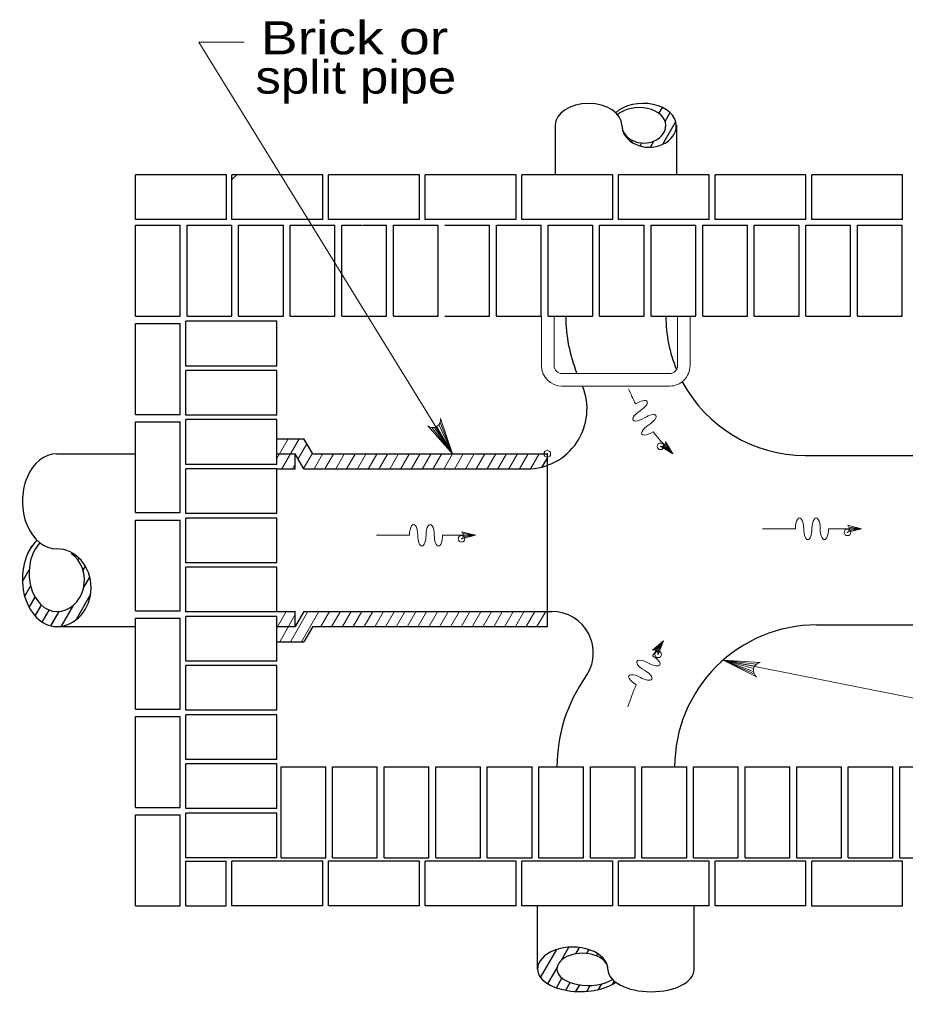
# Model space of a CAD drawing. Extents: x 750.7 to 784.7, y 860.1 to 882.1.
# Drawn here: x 767.038 to 771.324, y 862.671 to 867.382 of the extents above; entities that cross this region are included whole.
import ezdxf

# ---------------------------------------------------------------- set-up
doc = ezdxf.new("R2010")
doc.units = 0
doc.header["$LTSCALE"] = 0.064
doc.header["$PDMODE"] = 32
doc.header["$PDSIZE"] = 0.032
doc.layers.add('1', color=7, linetype='Continuous', lineweight=13)

msp = doc.modelspace()

# ---------------------------------------------------------------- linework, layer by layer
at = {"layer": '1', "lineweight": 25}
for p, q in [((770.13133, 866.92742), (770.148, 866.9565)), ((769.92375, 866.93008), (769.92617, 866.93433)), ((770.1615, 866.889), (770.18592, 866.93133)), ((769.62983, 866.87017), (769.62983, 866.63142)), ((770.15042, 866.77867), (770.21317, 866.88783)), ((770.21542, 866.87017), (770.21542, 866.63142)), ((769.96617, 866.82208), (769.96783, 866.825)), ((769.99925, 866.78867), (770.00383, 866.7965)), ((770.04075, 866.76983), (770.04933, 866.78475)), ((770.08975, 866.76408), (770.10683, 866.79383)), ((768.03883, 866.63142), (767.59925, 866.63142)), ((767.59925, 866.41508), (767.59925, 866.63142)), ((768.03883, 866.41508), (768.03883, 866.63142)), ((768.06542, 866.60733), (768.09075, 866.63158)), ((768.06542, 866.41508), (768.06542, 866.63142)), ((768.50492, 866.63142), (768.06542, 866.63142)), ((768.50492, 866.41508), (768.50492, 866.63142)), ((768.53292, 866.41508), (768.53292, 866.63142)), ((768.68067, 866.63142), (768.53292, 866.63142)), ((768.97242, 866.63142), (768.63892, 866.63142)), ((768.97242, 866.41508), (768.97242, 866.63142)), ((769.44, 866.63142), (769.00042, 866.63142)), ((769.00042, 866.41508), (769.00042, 866.63142)), ((769.44, 866.41508), (769.44, 866.63142)), ((769.9075, 866.63142), (769.46792, 866.63142)), ((769.46792, 866.41508), (769.46792, 866.63142)), ((769.9075, 866.41508), (769.9075, 866.63142)), ((770.375, 866.63142), (769.93542, 866.63142)), ((769.93542, 866.41508), (769.93542, 866.63142)), ((770.375, 866.41508), (770.375, 866.63142)), ((770.8425, 866.63142), (770.403, 866.63142)), ((770.403, 866.41508), (770.403, 866.63142)), ((770.8425, 866.41508), (770.8425, 866.63142)), ((771.31008, 866.63142), (770.8705, 866.63142)), ((770.8705, 866.41508), (770.8705, 866.63142)), ((771.31008, 866.41508), (771.31008, 866.63142)), ((768.03883, 866.41508), (767.59925, 866.41508)), ((767.59925, 866.38717), (767.81558, 866.38717)), ((767.59925, 865.94758), (767.59925, 866.38717)), ((767.84875, 865.94758), (767.84875, 866.38717)), ((767.84875, 866.38717), (768.065, 866.38717)), ((768.065, 865.94758), (768.065, 866.38717)), ((768.50492, 866.41508), (768.06542, 866.41508)), ((768.09817, 865.94758), (768.09817, 866.38717)), ((768.09817, 866.38717), (768.31442, 866.38717)), ((768.31442, 865.94758), (768.31442, 866.38717)), ((768.34758, 865.94758), (768.34758, 866.38717)), ((768.34758, 866.38717), (768.56392, 866.38717)), ((768.71075, 866.41508), (768.53292, 866.41508)), ((768.56392, 865.94758), (768.56392, 866.38717)), ((768.597, 865.94758), (768.597, 866.38717)), ((768.597, 866.38717), (768.69567, 866.38717)), ((768.97242, 866.41508), (768.68792, 866.41508)), ((768.69842, 866.38717), (768.81333, 866.38717)), ((768.81333, 865.94758), (768.81333, 866.38717)), ((768.8465, 865.94758), (768.8465, 866.38717)), ((768.8465, 866.38717), (769.06275, 866.38717)), ((769.44, 866.41508), (769.00042, 866.41508)), ((769.06275, 865.94758), (769.06275, 866.38717)), ((769.09592, 866.38717), (769.31225, 866.38717)), ((769.31225, 865.94758), (769.31225, 866.38717)), ((769.34533, 865.94758), (769.34533, 866.38717)), ((769.34533, 866.38717), (769.56167, 866.38717)), ((769.9075, 866.41508), (769.46792, 866.41508)), ((769.56167, 865.94758), (769.56167, 866.38717)), ((769.59483, 865.94758), (769.59483, 866.38717)), ((769.59483, 866.38717), (769.81108, 866.38717)), ((769.81108, 865.94758), (769.81108, 866.38717)), ((769.84425, 865.94758), (769.84425, 866.38717)), ((769.84425, 866.38717), (770.06058, 866.38717)), ((770.375, 866.41508), (769.93542, 866.41508)), ((770.06058, 865.94758), (770.06058, 866.38717)), ((770.09367, 865.94758), (770.09367, 866.38717)), ((770.09367, 866.38717), (770.31, 866.38717)), ((770.31, 865.94758), (770.31, 866.38717)), ((770.34317, 865.94758), (770.34317, 866.38717)), ((770.34317, 866.38717), (770.55942, 866.38717)), ((770.8425, 866.41508), (770.403, 866.41508)), ((770.55942, 865.94758), (770.55942, 866.38717)), ((770.59258, 865.94758), (770.59258, 866.38717)), ((770.59258, 866.38717), (770.80883, 866.38717)), ((770.80883, 865.94758), (770.80883, 866.38717)), ((770.842, 865.94758), (770.842, 866.38717)), ((770.842, 866.38717), (771.05833, 866.38717)), ((771.31008, 866.41508), (770.8705, 866.41508)), ((771.05833, 865.94758), (771.05833, 866.38717)), ((771.0915, 865.94758), (771.0915, 866.38717)), ((771.0915, 866.38717), (771.30775, 866.38717)), ((771.30775, 865.94758), (771.30775, 866.38717)), ((767.59925, 865.91183), (767.81558, 865.91192)), ((767.59925, 865.47233), (767.59925, 865.91183)), ((768.28308, 865.92225), (767.8435, 865.92225)), ((767.8435, 865.706), (767.8435, 865.92225)), ((767.84875, 865.94758), (768.065, 865.94758)), ((768.09817, 865.94758), (768.31442, 865.94758)), ((768.28308, 865.706), (768.28308, 865.92225)), ((768.34758, 865.94758), (768.56392, 865.94758)), ((768.597, 865.94758), (768.81333, 865.94758)), ((768.8465, 865.94758), (769.06275, 865.94758)), ((769.09592, 865.94758), (769.31225, 865.94758)), ((769.34533, 865.94758), (769.56167, 865.94758)), ((769.59483, 865.94758), (769.81108, 865.94758)), ((769.68058, 865.94758), (769.68058, 865.94742)), ((769.84425, 865.94758), (770.06058, 865.94758)), ((770.09367, 865.94758), (770.31, 865.94758)), ((770.16467, 865.94758), (770.16467, 865.94733)), ((770.34317, 865.94758), (770.55942, 865.94758)), ((770.59258, 865.94758), (770.80883, 865.94758)), ((770.842, 865.94758), (771.05833, 865.94758)), ((771.0915, 865.94758), (771.30775, 865.94758)), ((768.28308, 865.706), (767.8435, 865.706)), ((768.28308, 865.6845), (767.8435, 865.6845)), ((767.8435, 865.46817), (767.8435, 865.6845)), ((768.28308, 865.46817), (768.28308, 865.6845)), ((767.59925, 865.43658), (767.81558, 865.43658)), ((767.59925, 864.997), (767.59925, 865.43658)), ((768.28308, 865.46817), (767.8435, 865.46817)), ((768.28308, 865.44667), (767.8435, 865.44667)), ((767.8435, 865.23033), (767.8435, 865.44667)), ((768.28308, 865.23033), (768.28308, 865.44667)), ((768.28308, 865.35442), (768.414, 865.35442)), ((768.45633, 865.28142), (768.414, 865.35442)), ((767.21842, 865.28142), (767.59925, 865.28142)), ((768.28308, 865.28142), (768.372, 865.28142)), ((768.41433, 865.2085), (768.372, 865.28142)), ((768.372, 865.2085), (768.372, 865.28142)), ((768.45633, 865.28142), (769.59142, 865.28142)), ((769.567, 865.21808), (769.59142, 865.26042)), ((770.83842, 865.27358), (771.57217, 865.27358)), ((768.28308, 865.23033), (767.8435, 865.23033)), ((768.28308, 865.20883), (767.8435, 865.20883)), ((767.8435, 864.9925), (767.8435, 865.20883)), ((768.28308, 864.9925), (768.28308, 865.20883)), ((768.28308, 865.2085), (768.372, 865.2085)), ((768.41433, 865.2085), (769.49308, 865.2085)), ((768.28308, 864.9925), (767.8435, 864.9925)), ((768.28308, 864.971), (767.8435, 864.971)), ((767.8435, 864.75475), (767.8435, 864.971)), ((768.28308, 864.75475), (768.28308, 864.971)), ((767.59925, 864.96133), (767.81558, 864.96133)), ((767.59925, 864.52175), (767.59925, 864.96133)), ((767.08, 864.80275), (767.09758, 864.83342)), ((767.09758, 864.83967), (767.10025, 864.83808)), ((767.32117, 864.76758), (767.32642, 864.77675)), ((767.34542, 864.71875), (767.35667, 864.73833)), ((768.28308, 864.75475), (767.8435, 864.75475)), ((768.28308, 864.73317), (767.8435, 864.73317)), ((767.8435, 864.51692), (767.8435, 864.73317)), ((768.28308, 864.51692), (768.28308, 864.73317)), ((767.05242, 864.66392), (767.085, 864.72058)), ((767.34825, 864.63267), (767.37833, 864.68517)), ((767.0635, 864.59225), (767.09217, 864.64208)), ((767.085, 864.53867), (767.11367, 864.58858)), ((767.31167, 864.47825), (767.382, 864.60058)), ((767.11358, 864.49733), (767.14392, 864.55017)), ((767.24192, 864.44775), (767.3015, 864.5515)), ((767.1485, 864.46717), (767.18217, 864.52575)), ((767.19042, 864.44917), (767.23083, 864.5195)), ((768.28308, 864.51692), (767.8435, 864.51692)), ((768.28308, 864.49533), (767.8435, 864.49533)), ((767.8435, 864.27908), (767.8435, 864.49533)), ((768.28308, 864.51883), (768.372, 864.51883)), ((768.28308, 864.27908), (768.28308, 864.49533)), ((768.41433, 864.51883), (768.372, 864.44575)), ((768.372, 864.44575), (768.372, 864.51883)), ((768.41433, 864.51883), (769.6135, 864.51883)), ((767.21842, 864.44583), (767.59925, 864.44583)), ((767.59925, 864.486), (767.81558, 864.486)), ((767.59925, 864.0465), (767.59925, 864.486)), ((768.28308, 864.44575), (768.372, 864.44575)), ((768.45633, 864.44583), (768.414, 864.37292)), ((770.8935, 864.45367), (771.57217, 864.45367)), ((768.28308, 864.37292), (768.414, 864.37292)), ((768.28308, 864.27908), (767.8435, 864.27908)), ((768.28308, 864.25758), (767.8435, 864.25758)), ((767.8435, 864.04125), (767.8435, 864.25758)), ((768.28308, 864.04125), (768.28308, 864.25758)), ((768.28308, 864.04125), (767.8435, 864.04125)), ((767.59925, 864.01075), (767.81558, 864.01075)), ((767.59925, 863.57117), (767.59925, 864.01075)), ((768.28308, 864.01975), (767.8435, 864.01975)), ((767.8435, 863.80342), (767.8435, 864.01975)), ((768.28308, 863.80342), (768.28308, 864.01975)), ((768.28308, 863.80342), (767.8435, 863.80342)), ((768.28308, 863.78192), (767.8435, 863.78192)), ((767.8435, 863.56567), (767.8435, 863.78192)), ((768.28308, 863.56567), (768.28308, 863.78192)), ((768.30325, 863.32775), (768.30325, 863.76733)), ((768.30325, 863.76733), (768.5195, 863.76733)), ((768.5195, 863.32775), (768.5195, 863.76733)), ((768.55267, 863.32775), (768.55267, 863.76733)), ((768.55267, 863.76733), (768.769, 863.76733)), ((768.769, 863.32775), (768.769, 863.76733)), ((768.80217, 863.32775), (768.80217, 863.76733)), ((768.80217, 863.76733), (769.01842, 863.76733)), ((769.01842, 863.32775), (769.01842, 863.76733)), ((769.05158, 863.32775), (769.05158, 863.76733)), ((769.05158, 863.76733), (769.26783, 863.76733)), ((769.26783, 863.32775), (769.26783, 863.76733)), ((769.301, 863.32775), (769.301, 863.76733)), ((769.301, 863.76733), (769.51733, 863.76733)), ((769.51733, 863.32775), (769.51733, 863.76733)), ((769.5505, 863.32775), (769.5505, 863.76733)), ((769.5505, 863.76733), (769.76675, 863.76733)), ((769.638, 863.76733), (769.638, 863.76742)), ((769.76675, 863.32775), (769.76675, 863.76733)), ((769.79992, 863.32775), (769.79992, 863.76733)), ((769.79992, 863.76733), (770.01617, 863.76733)), ((770.01617, 863.32775), (770.01617, 863.76733)), ((770.04933, 863.32775), (770.04933, 863.76733)), ((770.04933, 863.76733), (770.26567, 863.76733)), ((770.20725, 863.76733), (770.20725, 863.7675)), ((770.26567, 863.32775), (770.26567, 863.76733)), ((770.29875, 863.32775), (770.29875, 863.76733)), ((770.29875, 863.76733), (770.51508, 863.76733)), ((770.51508, 863.32775), (770.51508, 863.76733)), ((770.54825, 863.32775), (770.54825, 863.76733)), ((770.54825, 863.76733), (770.7645, 863.76733)), ((770.7645, 863.32775), (770.7645, 863.76733)), ((770.79767, 863.32775), (770.79767, 863.76733)), ((770.79767, 863.76733), (771.014, 863.76733)), ((771.014, 863.32775), (771.014, 863.76733)), ((771.04708, 863.32775), (771.04708, 863.76733)), ((771.04708, 863.76733), (771.26342, 863.76733)), ((771.26342, 863.32775), (771.26342, 863.76733)), ((771.29658, 863.32775), (771.29658, 863.76733)), ((771.29658, 863.76733), (771.51283, 863.76733)), ((768.28308, 863.56567), (767.8435, 863.56567)), ((767.59925, 863.53542), (767.81558, 863.53542)), ((767.59925, 863.09592), (767.59925, 863.53542)), ((767.81558, 863.09592), (767.81558, 863.53542)), ((768.28308, 863.54408), (767.8435, 863.54408)), ((767.8435, 863.32783), (767.8435, 863.54408)), ((768.28308, 863.54408), (767.8435, 863.54408)), ((767.8435, 863.32783), (767.8435, 863.54408)), ((768.28308, 863.32783), (768.28308, 863.54408)), ((768.28308, 863.32783), (768.28308, 863.54408)), ((768.28308, 863.32783), (767.8435, 863.32783)), ((768.28308, 863.32783), (767.8435, 863.32783)), ((768.30325, 863.32775), (768.5195, 863.32775)), ((768.55267, 863.32775), (768.769, 863.32775)), ((768.80217, 863.32775), (769.01842, 863.32775)), ((769.05158, 863.32775), (769.26783, 863.32775)), ((769.301, 863.32775), (769.51733, 863.32775)), ((769.5505, 863.32775), (769.76675, 863.32775)), ((769.79992, 863.32775), (770.01617, 863.32775)), ((770.04933, 863.32775), (770.26567, 863.32775)), ((770.29875, 863.32775), (770.51508, 863.32775)), ((770.54825, 863.32775), (770.7645, 863.32775)), ((770.79767, 863.32775), (771.014, 863.32775)), ((771.04708, 863.32775), (771.26342, 863.32775)), ((771.29658, 863.32775), (771.51283, 863.32775)), ((768.03742, 863.09592), (768.03742, 863.31183)), ((768.06542, 863.09567), (768.06542, 863.31183)), ((768.53292, 863.0955), (768.53292, 863.31158)), ((769.00042, 863.09533), (769.00042, 863.31142)), ((769.46792, 863.09517), (769.46792, 863.31125)), ((769.93542, 863.09492), (769.93542, 863.31108)), ((770.403, 863.09475), (770.403, 863.31083)), ((770.8705, 863.09458), (770.8705, 863.31067)), ((767.59925, 863.09592), (767.81558, 863.09592)), ((767.8435, 863.09592), (768.03742, 863.09592)), ((768.50492, 863.09567), (768.06542, 863.09567)), ((768.97242, 863.0955), (768.53292, 863.0955)), ((769.44, 863.09533), (769.00042, 863.09533)), ((769.9075, 863.09517), (769.46792, 863.09517)), ((769.54367, 862.78842), (769.54367, 863.09533)), ((770.375, 863.09492), (769.93542, 863.09492)), ((770.30158, 862.78842), (770.30158, 863.09492)), ((770.8425, 863.09475), (770.403, 863.09475)), ((771.31008, 863.09458), (770.8705, 863.09458)), ((769.65983, 862.83258), (769.69583, 862.89525)), ((769.72992, 862.86358), (769.74733, 862.89383)), ((769.55883, 862.748), (769.63692, 862.88425)), ((769.783, 862.865), (769.79367, 862.8835)), ((769.82875, 862.85358), (769.83492, 862.86433)), ((769.86675, 862.82883), (769.86925, 862.83317)), ((769.594, 862.71817), (769.6385, 862.79533)), ((769.63533, 862.69908), (769.66225, 862.74575)), ((769.68075, 862.68708), (769.70225, 862.72433)), ((769.72967, 862.68117), (769.74808, 862.71308)), ((769.78225, 862.68158), (769.79883, 862.71033)), ((769.83958, 862.69033), (769.85567, 862.71817)), ((769.90658, 862.71558), (769.91558, 862.73133))]:
    msp.add_line(p, q, dxfattribs=at)
at = {"layer": '1'}
for p, q in [((769.56358, 865.94758), (769.56358, 865.70733)), ((769.62417, 865.94758), (769.62417, 865.70733)), ((770.22108, 865.94758), (770.22108, 865.70733)), ((770.28167, 865.94758), (770.28167, 865.70733)), ((769.662, 865.66958), (770.18325, 865.66958)), ((769.662, 865.60892), (770.18325, 865.60892)), ((769.03283, 865.40825), (769.13242, 865.28058)), ((769.04517, 865.40908), (769.13242, 865.28058)), ((769.05575, 865.41325), (769.13242, 865.28058)), ((769.06683, 865.42292), (769.13242, 865.28058)), ((769.07275, 865.43342), (769.13242, 865.28058)), ((768.28308, 865.2585), (768.33825, 865.35442)), ((768.30667, 865.2085), (768.3905, 865.35442)), ((768.3865, 865.2565), (768.4285, 865.3295)), ((770.19817, 865.28233), (770.15733, 865.32358)), ((768.41275, 865.21117), (768.45475, 865.28417)), ((768.4635, 865.2085), (768.50425, 865.27942)), ((768.51583, 865.2085), (768.55658, 865.2795)), ((768.56808, 865.2085), (768.60892, 865.27958)), ((768.62033, 865.2085), (768.66133, 865.27967)), ((768.67267, 865.2085), (768.71367, 865.27983)), ((768.72408, 865.207), (768.766, 865.27992)), ((768.77642, 865.20717), (768.81833, 865.28)), ((768.82883, 865.20725), (768.87067, 865.28008)), ((768.88117, 865.20733), (768.923, 865.28017)), ((768.9335, 865.20742), (768.97533, 865.28033)), ((768.98583, 865.2075), (769.02767, 865.28042)), ((769.03817, 865.20767), (769.08008, 865.2805)), ((769.0905, 865.20775), (769.13242, 865.28058)), ((769.14283, 865.20783), (769.18475, 865.28067)), ((769.19517, 865.20792), (769.23708, 865.28075)), ((769.24758, 865.208), (769.28942, 865.28092)), ((769.29992, 865.20817), (769.34175, 865.281)), ((769.35225, 865.20825), (769.39408, 865.28108)), ((769.40458, 865.20833), (769.44642, 865.28117)), ((769.45692, 865.20842), (769.49883, 865.28125)), ((769.50925, 865.2085), (769.55117, 865.28142)), ((768.35892, 865.2085), (768.372, 865.23125)), ((770.63142, 864.91883), (770.79142, 864.91883)), ((770.9515, 864.91883), (771.1115, 864.91883)), ((771.11008, 864.91883), (771.052, 864.91883)), ((768.7645, 864.88767), (768.92458, 864.88767)), ((769.08458, 864.88767), (769.24458, 864.88767)), ((769.24317, 864.88767), (769.18508, 864.88767)), ((768.28308, 864.43983), (768.3285, 864.51883)), ((768.29692, 864.37292), (768.372, 864.50358)), ((768.34917, 864.37292), (768.43317, 864.51892)), ((768.4015, 864.37292), (768.4855, 864.519)), ((768.49567, 864.44583), (768.53783, 864.51908)), ((768.548, 864.44583), (768.59017, 864.51925)), ((768.60025, 864.44583), (768.6425, 864.51933)), ((768.65258, 864.44583), (768.69483, 864.51942)), ((768.70483, 864.44583), (768.74717, 864.5195)), ((768.75625, 864.44425), (768.7995, 864.51958)), ((768.80858, 864.44433), (768.85183, 864.51975)), ((768.86092, 864.4445), (768.90425, 864.51983)), ((768.91325, 864.44458), (768.95658, 864.51992)), ((768.96558, 864.44467), (769.00892, 864.52)), ((769.01792, 864.44475), (769.06125, 864.52008)), ((769.07025, 864.44483), (769.11358, 864.52025)), ((769.12267, 864.445), (769.16592, 864.52033)), ((769.175, 864.44508), (769.21825, 864.52042)), ((769.22733, 864.44517), (769.27067, 864.5205)), ((769.27967, 864.44525), (769.323, 864.52058)), ((769.332, 864.44533), (769.37533, 864.52067)), ((769.38433, 864.44542), (769.42767, 864.52083)), ((769.43667, 864.44558), (769.48, 864.52092)), ((769.489, 864.44567), (769.53108, 864.51883)), ((769.54142, 864.44575), (769.58342, 864.51883)), ((770.15325, 864.37533), (770.11842, 864.32875)), ((770.58925, 864.24375), (770.44133, 864.28367)), ((770.58825, 864.22908), (770.44133, 864.28367)), ((770.5915, 864.2175), (770.44133, 864.28367)), ((770.59383, 864.25425), (770.44133, 864.28367)), ((770.602, 864.26358), (770.44133, 864.28367))]:
    msp.add_line(p, q, dxfattribs=at)
for points in [[(769.13242, 865.28058), (767.90633, 867.27175), (768.12433, 867.27175)], [(769.0745, 865.45167), (769.13242, 865.28058), (769.01317, 865.41625)], [(770.16333, 865.34167), (770.19917, 865.28133), (770.13917, 865.31775)], [(770.16233, 865.33058), (770.19917, 865.28133), (770.15042, 865.31842)], [(771.04333, 864.93583), (771.1115, 864.91883), (771.04333, 864.90183)], [(771.05058, 864.92733), (771.1115, 864.91883), (771.05083, 864.91033)], [(769.1765, 864.90467), (769.24458, 864.88767), (769.17642, 864.87075)], [(769.18367, 864.89617), (769.24458, 864.88767), (769.18392, 864.87917)], [(770.09967, 864.332), (770.15408, 864.37642), (770.12683, 864.31167)], [(770.11075, 864.33275), (770.15408, 864.37642), (770.12458, 864.32275)], [(770.60308, 864.20333), (770.44133, 864.28367), (770.6215, 864.27175)], [(770.44133, 864.28367), (772.43192, 863.8875), (772.72508, 863.8875)]]:
    msp.add_lwpolyline(points, dxfattribs=at)
at = {"layer": '1', "lineweight": 25}
for points in [[(767.59925, 865.94758), (767.81558, 865.94758), (767.81558, 866.38717)], [(767.59925, 865.47233), (767.81558, 865.47233), (767.81558, 865.91192)], [(767.59925, 864.997), (767.81558, 864.997), (767.81558, 865.43658)], [(768.45633, 864.44583), (769.59142, 864.44583), (769.59142, 865.28142)], [(767.59925, 864.52175), (767.81558, 864.52175), (767.81558, 864.96133)], [(767.59925, 864.0465), (767.81558, 864.0465), (767.81558, 864.486)], [(767.59925, 863.57117), (767.81558, 863.57117), (767.81558, 864.01075)], [(767.8435, 863.09592), (767.8435, 863.31183), (768.03742, 863.31183)], [(768.50492, 863.0955), (768.50492, 863.31183), (768.06542, 863.31183)], [(768.97242, 863.09533), (768.97242, 863.31158), (768.53292, 863.31158)], [(769.44, 863.09517), (769.44, 863.31142), (769.00042, 863.31142)], [(769.9075, 863.09492), (769.9075, 863.31125), (769.46792, 863.31125)], [(770.375, 863.09475), (770.375, 863.31108), (769.93542, 863.31108)], [(770.8425, 863.09458), (770.8425, 863.31083), (770.403, 863.31083)], [(771.31008, 863.09442), (771.31008, 863.31067), (770.8705, 863.31067)]]:
    msp.add_lwpolyline(points, dxfattribs=at)
for centre, radius, start, end in [((770.41944, 865.9474), 0.7389, 180.00014, 202.08794), ((770.83844, 865.94735), 0.67373, 180.00014, 202.55827), ((770.83844, 865.94735), 0.67373, 208.10223, 270.00008), ((769.49308, 865.49885), 0.29035, 270.00293, 22.27814), ((769.6135, 864.31854), 0.20028, 324.61372, 89.99999), ((770.89348, 863.76749), 0.6862, 90.00005, 180.00019), ((770.38934, 863.76745), 0.75136, 144.6134, 179.9999)]:
    msp.add_arc(centre, radius, start, end, dxfattribs=at)
at = {"layer": '1'}
for centre, radius, start, end in [((769.66197, 865.70733), 0.09841, 180.0002, 270.0001), ((769.66197, 865.70733), 0.03778, 180.00039, 270.00013), ((770.18328, 865.70733), 0.03778, 270.00019, 0.00039), ((770.18328, 865.70733), 0.09841, 270.00011, 0.0002), ((770.83844, 865.94735), 0.92338, 202.35823, 207.35732), ((769.03667, 865.44631), 0.03822, 232.08782, 7.91395), ((770.83844, 865.94735), 0.92317, 217.30128, 226.17561), ((770.89348, 863.76749), 0.9579, 140.52693, 145.91787), ((770.62612, 864.23384), 0.03822, 96.98629, 232.81241), ((770.89348, 863.76749), 0.95789, 155.50039, 162.31857)]:
    msp.add_arc(centre, radius, start, end, dxfattribs=at)
at = {"layer": '1', "lineweight": 25}
for centre, major_axis, ratio, start_param, end_param in [((769.79088, 866.87014), (-0.16102, 0), 0.659126, 3.1415927, 6.2831853), ((770.05437, 866.87014), (-0.16102, 0), 0.659126, 3.1415927, 5.6706266), ((770.03465, 866.87014), (-0.13005, 0), 0.659126, 3.1416016, 5.6315244), ((770.08364, 866.87014), (-0.13174, 0), 0.805599, 6.2831853, 9.424778), ((770.0583, 866.87014), (-0.1064, 0), 0.805599, 6.2831853, 9.424778), ((767.21844, 865.05166), (0, 0.22979), 0.723389, 6.2831853, 9.424778), ((767.21844, 864.67564), (0, 0.22979), 0.723389, 0.6125516, 3.1415927), ((767.21844, 864.70401), (0, 0.1852), 0.723389, 0.6520138, 3.1415932), ((767.21844, 864.63386), (0, 0.18801), 0.884137, 3.1415927, 6.2831853), ((767.21844, 864.67034), (0, 0.15153), 0.884137, 3.1415932, 5.740807), ((769.71419, 862.7884), (0.17054, 0), 0.630379, 6.2831853, 9.4363781), ((769.76135, 862.7884), (0.12338, 0), 0.630379, 6.2831853, 9.4259543), ((769.75208, 862.78801), (0.20844, -0.00039), 0.515758, 3.1415926, 5.6706255), ((769.78877, 862.78794), (0.1508, -0.00028), 0.515758, 3.1415851, 5.6130548), ((770.09317, 862.78736), (0.20844, -0.00039), 0.515758, 3.1415927, 6.2831853)]:
    msp.add_ellipse(centre, major_axis=major_axis, ratio=ratio, start_param=start_param, end_param=end_param, dxfattribs=at)
at = {"layer": '1'}
for centre, major_axis, ratio, start_param, end_param in [((770.02922, 865.50622), (0.04443, 0.02812), 0.380456, 4.712389, 7.8539816), ((770.05061, 865.47241), (0.04443, 0.02812), 0.380456, 1.5707963, 4.712389), ((770.072, 865.43861), (0.04443, 0.02812), 0.380456, 4.712389, 7.8539816), ((770.0934, 865.40481), (0.04443, 0.02812), 0.380456, 1.5707963, 4.712389), ((770.15125, 865.3297), (0.01207, 0.01197), 0.5, 3.3984695, 6.0297764), ((770.81146, 864.91882), (0, -0.05257), 0.380456, 1.5707963, 4.712389), ((770.89147, 864.91882), (0, -0.05257), 0.380456, 1.5707963, 4.712389), ((768.94454, 864.88771), (0, -0.05257), 0.380456, 1.5707963, 4.712389), ((769.02455, 864.88771), (0, -0.05257), 0.380456, 1.5707963, 4.712389), ((770.85146, 864.91882), (0, -0.05257), 0.380456, 4.712389, 7.8539816), ((770.93147, 864.91882), (0, -0.05257), 0.380456, 4.712389, 7.8539816), ((771.04338, 864.91882), (0, 0.017), 0.5, 3.3984695, 6.0297764), ((768.98455, 864.88771), (0, -0.05257), 0.380456, 4.712389, 7.8539816), ((769.06456, 864.88771), (0, -0.05257), 0.380456, 4.712389, 7.8539816), ((769.17647, 864.88771), (0, 0.017), 0.5, 3.3984695, 6.0297764), ((770.09034, 864.28683), (0.04585, -0.02572), 0.380456, 4.712389, 7.8539816), ((770.11328, 864.32188), (-0.01362, 0.01018), 0.499997, 3.3984702, 6.0297771), ((770.07076, 864.25194), (0.04585, -0.02572), 0.380456, 1.5707963, 4.712389), ((770.03162, 864.18216), (0.04585, -0.02572), 0.380456, 1.5707963, 4.712389), ((770.05119, 864.21705), (0.04585, -0.02572), 0.380456, 4.712389, 7.8539816)]:
    msp.add_ellipse(centre, major_axis=major_axis, ratio=ratio, start_param=start_param, end_param=end_param, dxfattribs=at)
for p in [(769.59142, 865.28142), (770.139, 865.31767), (771.04333, 864.90167), (769.17642, 864.87058), (770.127, 864.31158)]:
    msp.add_point(p, dxfattribs=at)

# ---------------------------------------------------------------- texts
for s, width, p in [('Brick or', 1.25, (768.20542, 867.21342)), ('split pipe', 1.15, (768.1795, 867.02342))]:
    msp.add_text(s, height=0.16, dxfattribs=dict(at, width=width)).set_placement(p)

doc.saveas('drawing.dxf')
